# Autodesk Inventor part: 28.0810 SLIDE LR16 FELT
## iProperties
Created: 2009-01
Part Number: 28.0810 SLIDE LR16 FELT
Document SubType Name: Modeling
Designer: Administrator
Density: 1 g/cm^3
Author: Administrator
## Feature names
1. Base1
